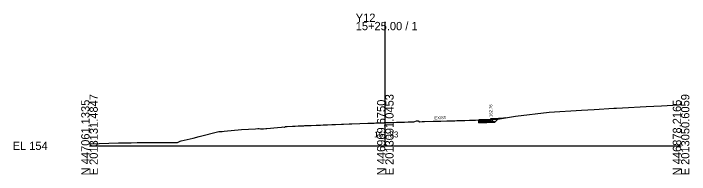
# Model space of a CAD drawing. Extents: x -26 to 1203, y -10 to 9542.
# Drawn here: x 974.3 to 1202.8, y 490.3 to 544.7 of the extents above; entities that cross this region are included whole.
import ezdxf

# ---------------------------------------------------------------- set-up
doc = ezdxf.new("R2010")
doc.units = 0
for name, color, linetype in [('Default', 7, 'Continuous'), ('Exist Cross Section Cell', 7, 'Continuous'), ('Exist XS Center Line Elevation Label', 7, 'Continuous'), ('Exist XS Ground Line', 7, 'Continuous'), ('Prop CMT Conc Surface', 7, 'Continuous'), ('Prop CMT Concrete Structures', 7, 'Continuous'), ('Prop CMT Pvmt Course 1', 7, 'Continuous'), ('Prop CMT Pvmt Course 1 CG', 7, 'Continuous'), ('Prop CMT Pvmt Course 2', 7, 'Continuous'), ('Prop CMT Pvmt Course 3', 7, 'Continuous'), ('Prop CMT Pvmt Surface', 7, 'Continuous'), ('Prop CMT Slope Grass', 7, 'Continuous'), ('Prop CMT Subgrade Earthwork', 7, 'Continuous'), ('Prop XS Earthwork Shape', 7, 'Continuous'), ('Prop XS Hydro Elevations', 7, 'Continuous'), ('Prop XS SE Text', 7, 'Continuous')]:
    doc.layers.add(name, color=color, linetype=linetype)

msp = doc.modelspace()

# ---------------------------------------------------------------- linework, layer by layer
at = {"layer": 'Exist Cross Section Cell'}
for p, q in [((1100, 500), (1100, 541.89)), ((1000, 500), (1100, 500)), ((1100, 500), (1200, 500))]:
    msp.add_line(p, q, dxfattribs=at)
at = {"layer": 'Exist XS Ground Line'}
msp.add_lwpolyline([(1000, 500.63), (1009.78, 500.97), (1011.66, 500.99), (1014.08, 501.02), (1016.15, 501.07), (1018.73, 501.1), (1021.34, 501.12), (1024.12, 501.15), (1026.19, 501.17), (1026.77, 501.16), (1027.25, 501.15), (1028.52, 501.12), (1029.76, 501.1), (1030.65, 501.6), (1030.98, 501.67), (1035.07, 502.61), (1037.07, 503.13), (1043.71, 504.8), (1044.85, 504.89), (1045.54, 504.94), (1051.44, 505.49), (1056.08, 505.77), (1056.95, 505.8), (1057.34, 505.8), (1057.78, 505.75), (1058.87, 505.79), (1059.61, 505.82), (1059.93, 505.83), (1063.54, 506.17), (1064.89, 506.31), (1065.41, 506.39), (1065.88, 506.26), (1066.31, 506.48), (1066.79, 506.51), (1068.65, 506.61), (1069.5, 506.65), (1070.53, 506.71), (1072.44, 506.8), (1072.85, 506.82), (1074.34, 506.89), (1074.98, 506.92), (1076.65, 506.99), (1077.04, 507.01), (1077.78, 507.02), (1078.13, 507.03), (1079.05, 507.07), (1080.03, 507.1), (1080.46, 507.12), (1081.93, 507.18), (1083.19, 507.22), (1085.21, 507.3), (1085.91, 507.32), (1087.8, 507.4), (1088.63, 507.43), (1091.41, 507.54), (1094.08, 507.65), (1096.21, 507.71), (1096.82, 507.72), (1097.15, 507.74), (1098.64, 507.78), (1099.56, 507.82), (1100, 507.83), (1100.83, 507.86), (1102.29, 507.91), (1103.76, 507.95), (1105.01, 507.99), (1106.51, 508.03), (1107.74, 508.08), (1108.35, 508.1), (1109.6, 508.15), (1109.94, 508.18), (1110.54, 508.48), (1111.1, 508.44), (1111.7, 508.14), (1112.52, 508.23), (1113.28, 508.25), (1116.16, 508.31), (1118.72, 508.36), (1120.76, 508.43), (1121.46, 508.45), (1121.89, 508.46), (1122.68, 508.48), (1123.51, 508.5), (1124.17, 508.52), (1125.49, 508.56), (1126.88, 508.6), (1128.48, 508.64), (1129.62, 508.67), (1130.52, 508.69), (1132.35, 508.75), (1132.87, 508.77), (1133.68, 508.78), (1134.45, 508.81), (1135.36, 508.84), (1136.51, 508.93), (1138.63, 509.1), (1143.98, 510.06), (1155.44, 511.38), (1166.36, 512.06), (1170.59, 512.3), (1177.3, 512.72), (1178.17, 512.77), (1180.14, 512.89), (1188.23, 513.34), (1193.34, 513.55), (1199.17, 513.91), (1200, 513.96)], dxfattribs=at)
at = {"layer": 'Prop CMT Conc Surface'}
msp.add_lwpolyline([(1133.68, 508.78), (1135.68, 508.76), (1135.68, 509.26), (1136.18, 509.26)], dxfattribs=at)
at = {"layer": 'Prop CMT Concrete Structures'}
for points in [[(1133.68, 508.78), (1135.68, 508.76), (1135.68, 509.26), (1136.18, 509.26)], [(1136.18, 509.26), (1136.18, 508.27), (1133.68, 508.19)], [(1133.68, 508.19), (1133.68, 508.78)]]:
    msp.add_lwpolyline(points, dxfattribs=at)
at = {"layer": 'Prop CMT Pvmt Course 1'}
for points in [[(1131.66, 508.71), (1133.68, 508.78)], [(1131.66, 508.71), (1131.66, 508.71)], [(1131.66, 508.46), (1131.66, 508.71)], [(1133.68, 508.53), (1131.66, 508.46)], [(1133.68, 508.78), (1133.68, 508.53)]]:
    msp.add_lwpolyline(points, dxfattribs=at)
at = {"layer": 'Prop CMT Pvmt Course 1 CG'}
for points in [[(1133.68, 508.19), (1136.68, 508.29), (1137, 507.97)], [(1133.68, 507.86), (1133.68, 508.19)], [(1137, 507.97), (1133.68, 507.86)]]:
    msp.add_lwpolyline(points, dxfattribs=at)
at = {"layer": 'Prop CMT Pvmt Course 2'}
for points in [[(1131.66, 508.46), (1133.68, 508.53)], [(1131.66, 508.13), (1131.66, 508.46)], [(1133.68, 508.19), (1131.66, 508.13)], [(1133.68, 508.53), (1133.68, 508.19)]]:
    msp.add_lwpolyline(points, dxfattribs=at)
at = {"layer": 'Prop CMT Pvmt Course 3'}
for points in [[(1131.66, 508.13), (1133.68, 508.19)], [(1131.66, 507.79), (1131.66, 508.13)], [(1133.68, 507.86), (1131.66, 507.79)], [(1133.68, 508.19), (1133.68, 507.86)]]:
    msp.add_lwpolyline(points, dxfattribs=at)
at = {"layer": 'Prop CMT Pvmt Surface'}
msp.add_lwpolyline([(1131.66, 508.71), (1133.68, 508.78)], dxfattribs=at)
at = {"layer": 'Prop CMT Slope Grass'}
msp.add_lwpolyline([(1136.18, 509.26), (1140.62, 509.46)], dxfattribs=at)
at = {"layer": 'Prop CMT Subgrade Earthwork'}
for points in [[(1131.66, 507.79), (1131.66, 508.73)], [(1131.66, 507.79), (1133.68, 507.86)], [(1133.68, 507.86), (1131.66, 507.79)], [(1133.68, 507.86), (1137, 507.97), (1138.39, 509.36)]]:
    msp.add_lwpolyline(points, dxfattribs=at)
at = {"layer": 'Prop XS Earthwork Shape'}
for points in [[(1131.66, 508.73), (1131.66, 507.79), (1137, 507.97), (1138.09, 509.06), (1135.36, 508.84), (1134.45, 508.81), (1133.68, 508.78), (1132.87, 508.77), (1132.35, 508.75)], [(1138.09, 509.06), (1138.39, 509.36), (1140.62, 509.46), (1138.63, 509.1)]]:
    msp.add_lwpolyline(points, close=True, dxfattribs=at)

# ---------------------------------------------------------------- texts
at = {"layer": 'Default'}
msp.add_text('-', height=0.0001, dxfattribs=at).set_placement((1000, 500))
at = {"layer": 'Exist Cross Section Cell'}
for s, p in [('Y12', (1090, 541.89)), ('15+25.00 / 1', (1090, 539.09)), ('EL 154', (974, 498.6))]:
    msp.add_text(s, height=2.8, dxfattribs=at).set_placement(p)
for s, p in [('E 2013131.4847', (1002.8, 490)), ('E 2013091.0453', (1102.8, 490)), ('E 2013050.6059', (1202.8, 490)), ('N 447061.1335', (1000, 490)), ('N 446969.6750', (1100, 490)), ('N 446878.2165', (1200, 490))]:
    msp.add_text(s, height=2.8, rotation=90, dxfattribs=at).set_placement(p)
at = {"layer": 'Exist XS Center Line Elevation Label'}
msp.add_text('161.83', height=2, dxfattribs=at).set_placement((1096.23, 502.83))
at = {"layer": 'Prop XS Hydro Elevations'}
msp.add_text('162.76', height=1, rotation=90, dxfattribs=at).set_placement((1136.18, 509.76))
at = {"layer": 'Prop XS SE Text'}
msp.add_text('EXIST', height=1, rotation=1.8605, dxfattribs=at).set_placement((1116.63, 508.92))

doc.saveas('drawing.dxf')
